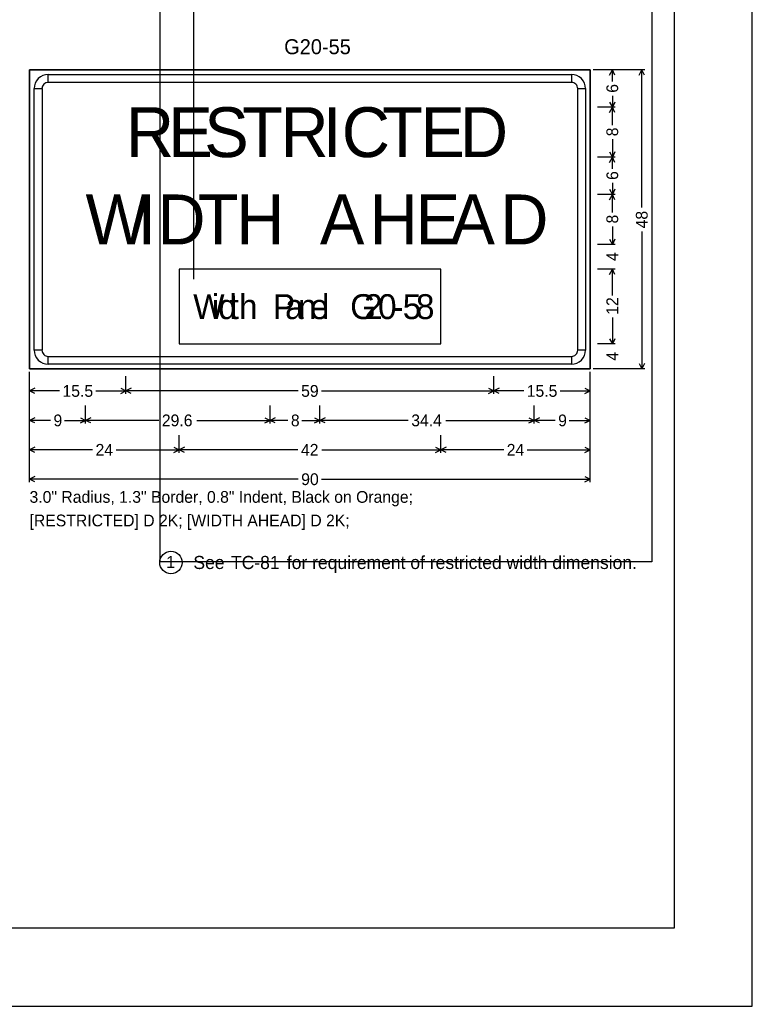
# Model space of a CAD drawing. Extents: x -1403959 to 81668, y -1400582 to 11018.
# Drawn here: x -1401594 to -1400615, y -1400582 to -1399262 of the extents above; entities that cross this region are included whole.
import ezdxf

# ---------------------------------------------------------------- set-up
doc = ezdxf.new("R2010")
doc.units = 0
for name, color, linetype in [('tdCiInt', 7, 'Continuous'), ('tdCiIntRampCL', 7, 'Continuous'), ('tdCiPriRamp', 7, 'Continuous'), ('tdCiPriRampCL', 7, 'Continuous'), ('tdCoStPrkTxt', 7, 'Continuous'), ('tdRailNorfolk_South', 7, 'Continuous'), ('trf_Sign_Details_Border', 7, 'Continuous'), ('trf_Sign_Details_Dimensions', 7, 'Continuous')]:
    doc.layers.add(name, color=color, linetype=linetype)

msp = doc.modelspace()

# ---------------------------------------------------------------- linework, layer by layer
at = {"layer": 'tdCiInt'}
for p, q in [((-1401556.3, -1399345.7), (-1401556.3, -1399335.3)), ((-1400856.3, -1399335.3), (-1400856.3, -1399345.7)), ((-1401575, -1399354), (-1401564.6, -1399354)), ((-1400847.9, -1399354), (-1400837.5, -1399354)), ((-1401031.3, -1399595.7), (-1401381.3, -1399595.7)), ((-1401381.3, -1399595.7), (-1401381.3, -1399695.7)), ((-1401031.3, -1399695.7), (-1401031.3, -1399595.7)), ((-1401381.3, -1399695.7), (-1401031.3, -1399695.7)), ((-1401564.6, -1399704), (-1401575, -1399704)), ((-1401556.3, -1399722.8), (-1401556.3, -1399712.4)), ((-1400856.3, -1399712.4), (-1400856.3, -1399722.8)), ((-1400837.5, -1399704), (-1400847.9, -1399704))]:
    msp.add_line(p, q, dxfattribs=at)
for points in [[(-1401581.3, -1399729), (-1400831.3, -1399729), (-1400831.3, -1399329), (-1401581.3, -1399329), (-1401581.3, -1399729)], [(-1400856.3, -1399345.7), (-1401556.3, -1399345.7), (-1401556.3, -1399335.3), (-1400856.3, -1399335.3), (-1400856.3, -1399345.7)], [(-1401564.6, -1399354), (-1401564.6, -1399704), (-1401575, -1399704), (-1401575, -1399354), (-1401564.6, -1399354)], [(-1400847.9, -1399704), (-1400847.9, -1399354), (-1400837.5, -1399354), (-1400837.5, -1399704), (-1400847.9, -1399704)], [(-1401556.3, -1399712.4), (-1400856.3, -1399712.4), (-1400856.3, -1399722.8), (-1401556.3, -1399722.8), (-1401556.3, -1399712.4)]]:
    msp.add_lwpolyline(points, close=True, dxfattribs=at)
for centre, radius, start, end in [((-1401556.3, -1399354), 18.8, 90.0002, 179.9998), ((-1401556.3, -1399354), 8.33, 90.0002, 179.9998), ((-1400856.3, -1399354), 18.8, 0, 90.0002), ((-1400856.3, -1399354), 8.33, 0, 90.0002), ((-1401556.3, -1399704), 18.8, 179.9998, 270.0001), ((-1401556.3, -1399704), 8.33, 179.9998, 270.0001), ((-1400856.3, -1399704), 18.8, 270.0001, 0.0003), ((-1400856.3, -1399704), 8.33, 270.0001, 0.0003)]:
    msp.add_arc(centre, radius, start, end, dxfattribs=at)
at = {"layer": 'tdCiIntRampCL'}
msp.add_lwpolyline([(-1403958.5, -1400581.8), (-1400614.5, -1400581.8), (-1400614.5, -1397997.8), (-1403958.5, -1397997.8)], close=True, dxfattribs=at)
at = {"layer": 'tdCiPriRamp'}
msp.add_lwpolyline([(-1403854, -1398467.3), (-1400719, -1398467.3), (-1400719, -1400477.3), (-1403854, -1400477.3)], close=True, dxfattribs=at)
at = {"layer": 'tdCiPriRampCL'}
for p, q in [((-1401407.1, -1398517.3), (-1401407.1, -1399987.3)), ((-1400749, -1398517.3), (-1400749, -1399987.3)), ((-1401362.1, -1398617.3), (-1401362.1, -1399608.8)), ((-1400749, -1399987.3), (-1401407.1, -1399987.3))]:
    msp.add_line(p, q, dxfattribs=at)
at = {"layer": 'tdRailNorfolk_South'}
msp.add_circle((-1401392.1, -1399988.1), 15, dxfattribs=at)
at = {"layer": 'trf_Sign_Details_Border'}
for points in [[(-1401581.3, -1399329), (-1400831.3, -1399329), (-1400831.3, -1399729), (-1401581.3, -1399729)], [(-1401381.3, -1399695.7), (-1401031.3, -1399695.7), (-1401031.3, -1399595.7), (-1401381.3, -1399595.7)]]:
    msp.add_lwpolyline(points, close=True, dxfattribs=at)
at = {"layer": 'trf_Sign_Details_Dimensions'}
for p, q in [((-1400758.4, -1399329), (-1400827.3, -1399329)), ((-1400797.8, -1399329), (-1400821.4, -1399329)), ((-1400805.3, -1399336.1), (-1400801.7, -1399329)), ((-1400801.7, -1399344.6), (-1400801.7, -1399329)), ((-1400798.2, -1399336.1), (-1400801.7, -1399329)), ((-1400765.9, -1399336.1), (-1400762.4, -1399329)), ((-1400762.4, -1399513.1), (-1400762.4, -1399329)), ((-1400758.9, -1399336.1), (-1400762.4, -1399329)), ((-1400805.3, -1399372), (-1400801.7, -1399379)), ((-1400801.7, -1399363.5), (-1400801.7, -1399379)), ((-1400798.2, -1399372), (-1400801.7, -1399379)), ((-1400797.8, -1399379), (-1400821.4, -1399379)), ((-1400805.3, -1399386.1), (-1400801.7, -1399379)), ((-1400801.7, -1399403), (-1400801.7, -1399379)), ((-1400798.2, -1399386.1), (-1400801.7, -1399379)), ((-1400801.7, -1399421.7), (-1400801.7, -1399445.7)), ((-1400805.3, -1399438.7), (-1400801.7, -1399445.7)), ((-1400798.2, -1399438.7), (-1400801.7, -1399445.7)), ((-1400797.8, -1399445.7), (-1400821.4, -1399445.7)), ((-1400805.3, -1399452.7), (-1400801.7, -1399445.7)), ((-1400801.7, -1399461.2), (-1400801.7, -1399445.7)), ((-1400798.2, -1399452.7), (-1400801.7, -1399445.7)), ((-1400805.3, -1399488.7), (-1400801.7, -1399495.7)), ((-1400801.7, -1399480.2), (-1400801.7, -1399495.7)), ((-1400798.2, -1399488.7), (-1400801.7, -1399495.7)), ((-1400797.8, -1399495.7), (-1400821.4, -1399495.7)), ((-1400805.3, -1399502.7), (-1400801.7, -1399495.7)), ((-1400801.7, -1399519.7), (-1400801.7, -1399495.7)), ((-1400798.2, -1399502.7), (-1400801.7, -1399495.7)), ((-1400801.7, -1399538.4), (-1400801.7, -1399562.4)), ((-1400762.4, -1399545), (-1400762.4, -1399729)), ((-1400805.3, -1399555.3), (-1400801.7, -1399562.4)), ((-1400798.2, -1399555.3), (-1400801.7, -1399562.4)), ((-1400797.8, -1399562.4), (-1400821.4, -1399562.4)), ((-1400797.8, -1399595.7), (-1400821.4, -1399595.7)), ((-1400805.3, -1399602.7), (-1400801.7, -1399595.7)), ((-1400801.7, -1399630.9), (-1400801.7, -1399595.7)), ((-1400798.2, -1399602.7), (-1400801.7, -1399595.7)), ((-1400801.7, -1399660.5), (-1400801.7, -1399695.7)), ((-1400805.3, -1399688.7), (-1400801.7, -1399695.7)), ((-1400798.2, -1399688.7), (-1400801.7, -1399695.7)), ((-1400797.8, -1399695.7), (-1400821.4, -1399695.7)), ((-1400797.8, -1399695.7), (-1400821.4, -1399695.7)), ((-1400758.4, -1399729), (-1400827.3, -1399729)), ((-1400797.8, -1399729), (-1400821.4, -1399729)), ((-1400765.9, -1399722), (-1400762.4, -1399729)), ((-1400758.9, -1399722), (-1400762.4, -1399729)), ((-1401581.3, -1399880.6), (-1401581.3, -1399733)), ((-1401581.3, -1399762.5), (-1401581.3, -1399738.9)), ((-1401452.3, -1399762.5), (-1401452.3, -1399738.9)), ((-1400960.3, -1399762.5), (-1400960.3, -1399738.9)), ((-1400960.3, -1399762.5), (-1400960.3, -1399738.9)), ((-1400831.3, -1399880.6), (-1400831.3, -1399733)), ((-1400831.3, -1399762.5), (-1400831.3, -1399738.9)), ((-1401574.2, -1399755), (-1401581.3, -1399758.6)), ((-1401459.3, -1399755), (-1401452.3, -1399758.6)), ((-1401445.2, -1399755), (-1401452.3, -1399758.6)), ((-1400967.3, -1399755), (-1400960.3, -1399758.6)), ((-1400953.2, -1399755), (-1400960.3, -1399758.6)), ((-1400838.3, -1399755), (-1400831.3, -1399758.6)), ((-1401541.2, -1399758.6), (-1401581.3, -1399758.6)), ((-1401574.2, -1399762.1), (-1401581.3, -1399758.6)), ((-1401492.4, -1399758.6), (-1401452.3, -1399758.6)), ((-1401459.3, -1399762.1), (-1401452.3, -1399758.6)), ((-1401221.9, -1399758.6), (-1401452.3, -1399758.6)), ((-1401445.2, -1399762.1), (-1401452.3, -1399758.6)), ((-1401190.6, -1399758.6), (-1400960.3, -1399758.6)), ((-1400967.3, -1399762.1), (-1400960.3, -1399758.6)), ((-1400920.2, -1399758.6), (-1400960.3, -1399758.6)), ((-1400953.2, -1399762.1), (-1400960.3, -1399758.6)), ((-1400871.4, -1399758.6), (-1400831.3, -1399758.6)), ((-1400838.3, -1399762.1), (-1400831.3, -1399758.6)), ((-1401581.3, -1399801.9), (-1401581.3, -1399778.2)), ((-1401506.3, -1399801.9), (-1401506.3, -1399778.2)), ((-1401259.6, -1399801.9), (-1401259.6, -1399778.2)), ((-1401192.9, -1399801.9), (-1401192.9, -1399778.2)), ((-1400906.3, -1399801.9), (-1400906.3, -1399778.2)), ((-1400906.3, -1399801.9), (-1400906.3, -1399778.2)), ((-1400831.3, -1399801.9), (-1400831.3, -1399778.2)), ((-1401574.2, -1399794.4), (-1401581.3, -1399797.9)), ((-1401513.3, -1399794.4), (-1401506.3, -1399797.9)), ((-1401499.2, -1399794.4), (-1401506.3, -1399797.9)), ((-1401266.6, -1399794.4), (-1401259.6, -1399797.9)), ((-1401252.6, -1399794.4), (-1401259.6, -1399797.9)), ((-1401200, -1399794.4), (-1401192.9, -1399797.9)), ((-1401185.9, -1399794.4), (-1401192.9, -1399797.9)), ((-1400913.3, -1399794.4), (-1400906.3, -1399797.9)), ((-1400899.2, -1399794.4), (-1400906.3, -1399797.9)), ((-1400838.3, -1399794.4), (-1400831.3, -1399797.9)), ((-1401553.1, -1399797.9), (-1401581.3, -1399797.9)), ((-1401574.2, -1399801.4), (-1401581.3, -1399797.9)), ((-1401534.4, -1399797.9), (-1401506.3, -1399797.9)), ((-1401513.3, -1399801.4), (-1401506.3, -1399797.9)), ((-1401408.3, -1399797.9), (-1401506.3, -1399797.9)), ((-1401499.2, -1399801.4), (-1401506.3, -1399797.9)), ((-1401357.6, -1399797.9), (-1401259.6, -1399797.9)), ((-1401266.6, -1399801.4), (-1401259.6, -1399797.9)), ((-1401235.6, -1399797.9), (-1401259.6, -1399797.9)), ((-1401252.6, -1399801.4), (-1401259.6, -1399797.9)), ((-1401216.9, -1399797.9), (-1401192.9, -1399797.9)), ((-1401200, -1399801.4), (-1401192.9, -1399797.9)), ((-1401074.6, -1399797.9), (-1401192.9, -1399797.9)), ((-1401185.9, -1399801.4), (-1401192.9, -1399797.9)), ((-1401024.6, -1399797.9), (-1400906.3, -1399797.9)), ((-1400913.3, -1399801.4), (-1400906.3, -1399797.9)), ((-1400878.1, -1399797.9), (-1400906.3, -1399797.9)), ((-1400899.2, -1399801.4), (-1400906.3, -1399797.9)), ((-1400859.4, -1399797.9), (-1400831.3, -1399797.9)), ((-1400838.3, -1399801.4), (-1400831.3, -1399797.9)), ((-1401581.3, -1399841.2), (-1401581.3, -1399817.6)), ((-1401381.3, -1399841.2), (-1401381.3, -1399817.6)), ((-1401031.3, -1399841.2), (-1401031.3, -1399817.6)), ((-1401031.3, -1399841.2), (-1401031.3, -1399817.6)), ((-1400831.3, -1399841.2), (-1400831.3, -1399817.6)), ((-1401574.2, -1399833.8), (-1401581.3, -1399837.3)), ((-1401388.3, -1399833.8), (-1401381.3, -1399837.3)), ((-1401374.2, -1399833.8), (-1401381.3, -1399837.3)), ((-1401038.3, -1399833.8), (-1401031.3, -1399837.3)), ((-1401024.2, -1399833.8), (-1401031.3, -1399837.3)), ((-1400838.3, -1399833.8), (-1400831.3, -1399837.3)), ((-1401497, -1399837.3), (-1401581.3, -1399837.3)), ((-1401574.2, -1399840.8), (-1401581.3, -1399837.3)), ((-1401465.6, -1399837.3), (-1401381.3, -1399837.3)), ((-1401388.3, -1399840.8), (-1401381.3, -1399837.3)), ((-1401222.2, -1399837.3), (-1401381.3, -1399837.3)), ((-1401374.2, -1399840.8), (-1401381.3, -1399837.3)), ((-1401190.4, -1399837.3), (-1401031.3, -1399837.3)), ((-1401038.3, -1399840.8), (-1401031.3, -1399837.3)), ((-1400947, -1399837.3), (-1401031.3, -1399837.3)), ((-1401024.2, -1399840.8), (-1401031.3, -1399837.3)), ((-1400915.6, -1399837.3), (-1400831.3, -1399837.3)), ((-1400838.3, -1399840.8), (-1400831.3, -1399837.3)), ((-1401574.2, -1399873.1), (-1401581.3, -1399876.7)), ((-1400838.3, -1399873.1), (-1400831.3, -1399876.7)), ((-1401221.9, -1399876.7), (-1401581.3, -1399876.7)), ((-1401574.2, -1399880.2), (-1401581.3, -1399876.7)), ((-1401190.7, -1399876.7), (-1400831.3, -1399876.7)), ((-1400838.3, -1399880.2), (-1400831.3, -1399876.7))]:
    msp.add_line(p, q, dxfattribs=at)

# ---------------------------------------------------------------- texts
at = {"layer": 'tdCiInt'}
for s, height, p in [('R', 66.7, (-1401452.3, -1399445.7)), ('E', 66.7, (-1401395.6, -1399445.7)), ('S', 66.7, (-1401347.6, -1399445.7)), ('T', 66.7, (-1401296.9, -1399445.7)), ('R', 66.7, (-1401245.6, -1399445.7)), ('I', 66.7, (-1401188.9, -1399445.7)), ('C', 66.7, (-1401163.6, -1399445.7)), ('T', 66.7, (-1401109.6, -1399445.7)), ('E', 66.7, (-1401058.3, -1399445.7)), ('D', 66.7, (-1401005.6, -1399445.7)), ('W', 66.7, (-1401506.3, -1399562.4)), ('I', 66.7, (-1401436.9, -1399562.4)), ('D', 66.7, (-1401410.3, -1399562.4)), ('T', 66.7, (-1401356.3, -1399562.4)), ('H', 66.7, (-1401304.9, -1399562.4)), ('A', 66.7, (-1401192.9, -1399562.4)), ('H', 66.7, (-1401126.3, -1399562.4)), ('E', 66.7, (-1401064.9, -1399562.4)), ('A', 66.7, (-1401018.3, -1399562.4)), ('D', 66.7, (-1400951.6, -1399562.4)), ('W', 33.3, (-1401362.4, -1399662.4)), ('i', 33.3, (-1401337.4, -1399662.4)), ('d', 33.3, (-1401328.8, -1399662.4)), ('t', 33.3, (-1401313.8, -1399662.4)), ('h', 33.3, (-1401301.1, -1399662.4)), ('P', 33.3, (-1401255.8, -1399662.4)), ('a', 33.3, (-1401239.4, -1399662.4)), ('n', 33.3, (-1401222.1, -1399662.4)), ('e', 33.3, (-1401206.1, -1399662.4)), ('l', 33.3, (-1401190.1, -1399662.4)), ('G', 33.3, (-1401152.4, -1399662.4)), ('2', 33.3, (-1401133.8, -1399662.4)), ('0', 33.3, (-1401115.1, -1399662.4)), ('5', 33.3, (-1401082.1, -1399662.4)), ('8', 33.3, (-1401064.4, -1399662.4)), ('-', 33.3, (-1401096.1, -1399662.4))]:
    msp.add_text(s, height=height, dxfattribs=at).set_placement(p)
at = {"layer": 'tdCoStPrkTxt'}
for s, height, p in [('1', 16, (-1401398.4, -1399995.3)), ('See ', 17.5, (-1401362.1, -1399996.8)), ('TC-81 ', 17.5, (-1401311.8, -1399996.8)), ('TC-81', 17.5, (-1401311.8, -1399996.8)), ('for requirement of restricted width dimension.', 17.5, (-1401237.1, -1399996.8))]:
    msp.add_text(s, height=height, dxfattribs=at).set_placement(p)
at = {"layer": 'tdRailNorfolk_South'}
msp.add_text('G20-55', height=20, dxfattribs=at).set_placement((-1401240.7, -1399308))
at = {"layer": 'trf_Sign_Details_Dimensions'}
for s, height, p in [('6', 15.7, (-1400793.9, -1399359.6)), ('8', 15.7, (-1400793.9, -1399417.8)), ('6', 15.7, (-1400793.9, -1399476.2)), ('48', 15.75, (-1400754.5, -1399541.1)), ('8', 15.7, (-1400793.9, -1399534.5)), ('4', 15.7, (-1400793.9, -1399584.7)), ('12', 15.75, (-1400793.9, -1399656.6)), ('4', 15.7, (-1400793.9, -1399718))]:
    msp.add_text(s, height=height, rotation=90.0002, dxfattribs=at).set_placement(p)
for s, height, p in [('15.5', 15.75, (-1401537.2, -1399766.4)), ('59', 15.75, (-1401218, -1399766.4)), ('15.5', 15.75, (-1400916.2, -1399766.4)), ('9', 15.7, (-1401549.2, -1399805.8)), ('29.6', 15.75, (-1401404.3, -1399805.8)), ('8', 15.7, (-1401231.7, -1399805.8)), ('34.4', 15.75, (-1401070.7, -1399805.8)), ('9', 15.7, (-1400874.2, -1399805.8)), ('24', 15.75, (-1401493, -1399845.2)), ('42', 15.75, (-1401218.2, -1399845.2)), ('24', 15.75, (-1400943, -1399845.2)), ('90', 15.75, (-1401217.9, -1399884.5)), ('3.0" Radius, 1.3" Border, 0.8" Indent, Black on Orange; ', 15.748, (-1401581.3, -1399908.2)), ('[RESTRICTED] D 2K; [WIDTH AHEAD] D 2K; ', 15.748, (-1401581.3, -1399939.7))]:
    msp.add_text(s, height=height, dxfattribs=at).set_placement(p)

doc.saveas('drawing.dxf')
